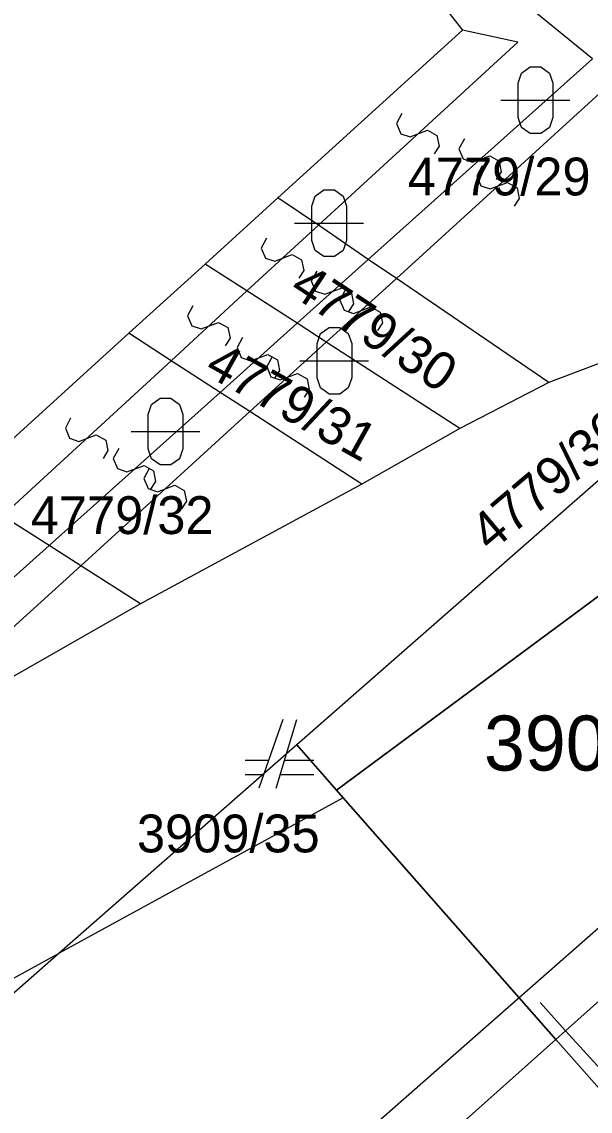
# Model space of a CAD drawing. Extents: x -266179 to -264727, y -1243225 to -1241702.
# Drawn here: x -265077.82 to -265061.28, y -1242723.44 to -1242691.75 of the extents above; entities that cross this region are included whole.
import ezdxf

# ---------------------------------------------------------------- set-up
doc = ezdxf.new("R2010")
doc.units = 0
doc.layers.add('Vrstva 1', color=7, linetype='Continuous')
doc.layers.add('Vrstva 2', color=7, linetype='Continuous')

msp = doc.modelspace()

# ---------------------------------------------------------------- linework, layer by layer
at = {"layer": 'Vrstva 1'}
for p, q in [((-265061.22, -1242692.83), (-265067.36, -1242687.8)), ((-265067.83, -1242688.37), (-265065, -1242691.99)), ((-265065, -1242691.99), (-265070.37, -1242696.87)), ((-265070.37, -1242696.87), (-265072.48, -1242698.8)), ((-265069.19, -1242697.67), (-265070.37, -1242696.87)), ((-265067.74, -1242698.66), (-265069.19, -1242697.67)), ((-265066.92, -1242699.22), (-265067.74, -1242698.66)), ((-265072.48, -1242698.8), (-265074.7, -1242700.81)), ((-265071.27, -1242699.58), (-265072.48, -1242698.8)), ((-265062.49, -1242702.24), (-265066.92, -1242699.22)), ((-265069.81, -1242700.52), (-265071.27, -1242699.58)), ((-265068.96, -1242701.07), (-265069.81, -1242700.52)), ((-265074.7, -1242700.81), (-265079.65, -1242705.31)), ((-265073.47, -1242701.61), (-265074.7, -1242700.81)), ((-265056.26, -1242700.89), (-265069.82, -1242712.78)), ((-265065.08, -1242703.58), (-265068.96, -1242701.07)), ((-265060.13, -1242701.35), (-265062.49, -1242702.24)), ((-265072.05, -1242702.53), (-265073.47, -1242701.61)), ((-265071.18, -1242703.09), (-265072.05, -1242702.53)), ((-265062.49, -1242702.24), (-265065.08, -1242703.58)), ((-265067.93, -1242705.2), (-265071.18, -1242703.09)), ((-265065.08, -1242703.58), (-265067.93, -1242705.2)), ((-265067.93, -1242705.2), (-265074.36, -1242708.68)), ((-265077.02, -1242706.98), (-265078.38, -1242706.12)), ((-265076.1, -1242707.57), (-265077.02, -1242706.98)), ((-265074.36, -1242708.68), (-265076.1, -1242707.57)), ((-265060.96, -1242708.4), (-265068.66, -1242714.1)), ((-265068.66, -1242714.1), (-265060.96, -1242708.4)), ((-265050.06, -1242708.47), (-265063.35, -1242720.14)), ((-265074.36, -1242708.68), (-265082.32, -1242713.22)), ((-265070.22, -1242712.04), (-265070.92, -1242714.04)), ((-265070.42, -1242714.04), (-265069.82, -1242712.04)), ((-265069.82, -1242712.78), (-265076.73, -1242718.84)), ((-265069.82, -1242712.78), (-265068.66, -1242714.1)), ((-265068.66, -1242714.1), (-265069.82, -1242712.78)), ((-265070.64, -1242713.24), (-265071.32, -1242713.24)), ((-265069.32, -1242713.24), (-265070.18, -1242713.24)), ((-265071.32, -1242713.64), (-265070.78, -1242713.64)), ((-265070.3, -1242713.64), (-265069.32, -1242713.64)), ((-265068.66, -1242714.1), (-265068.47, -1242714.32)), ((-265068.47, -1242714.32), (-265068.66, -1242714.1)), ((-265068.47, -1242714.32), (-265076.73, -1242718.84)), ((-265068.47, -1242714.32), (-265063.35, -1242720.14)), ((-265063.35, -1242720.14), (-265068.47, -1242714.32)), ((-265083.25, -1242722.41), (-265076.73, -1242718.84)), ((-265076.73, -1242718.84), (-265081.3, -1242722.85)), ((-265063.35, -1242720.14), (-265075.07, -1242730.43)), ((-265062.28, -1242721.35), (-265063.35, -1242720.14)), ((-265063.35, -1242720.14), (-265062.28, -1242721.35)), ((-265059.6, -1242724.4), (-265062.28, -1242721.35)), ((-265062.28, -1242721.35), (-265059.6, -1242724.4))]:
    msp.add_line(p, q, dxfattribs=at)
for points in [[(-265063.38, -1242693.53), (-265063.28, -1242693.24), (-265063.03, -1242693.06), (-265062.72, -1242693.06), (-265062.47, -1242693.24), (-265062.37, -1242693.53), (-265062.37, -1242694.53), (-265062.47, -1242694.82), (-265062.72, -1242695), (-265063.03, -1242695), (-265063.28, -1242694.82), (-265063.38, -1242694.53)], [(-265069.38, -1242697.11), (-265069.28, -1242696.82), (-265069.03, -1242696.64), (-265068.72, -1242696.64), (-265068.47, -1242696.82), (-265068.37, -1242697.11), (-265068.37, -1242698.11), (-265068.47, -1242698.4), (-265068.72, -1242698.58), (-265069.03, -1242698.58), (-265069.28, -1242698.4), (-265069.38, -1242698.11)], [(-265069.23, -1242701.11), (-265069.13, -1242700.82), (-265068.88, -1242700.64), (-265068.57, -1242700.64), (-265068.32, -1242700.82), (-265068.22, -1242701.11), (-265068.22, -1242702.11), (-265068.32, -1242702.4), (-265068.57, -1242702.58), (-265068.88, -1242702.58), (-265069.13, -1242702.4), (-265069.23, -1242702.11)], [(-265074.14, -1242703.17), (-265074.04, -1242702.88), (-265073.79, -1242702.7), (-265073.48, -1242702.7), (-265073.23, -1242702.88), (-265073.13, -1242703.17), (-265073.13, -1242704.17), (-265073.23, -1242704.46), (-265073.48, -1242704.64), (-265073.79, -1242704.64), (-265074.04, -1242704.46), (-265074.14, -1242704.17)]]:
    msp.add_lwpolyline(points, close=True, dxfattribs=at)
for points in [[(-265063.88, -1242694.03), (-265062.61, -1242694.03), (-265061.88, -1242694.03)], [(-265069.88, -1242697.61), (-265068.61, -1242697.61), (-265067.88, -1242697.61)], [(-265069.73, -1242701.61), (-265068.46, -1242701.61), (-265067.73, -1242701.61)], [(-265074.64, -1242703.67), (-265073.37, -1242703.67), (-265072.64, -1242703.67)]]:
    msp.add_lwpolyline(points, dxfattribs=at)
at = {"layer": 'Vrstva 2'}
for p, q in [((-265063.39, -1242692.34), (-265065, -1242691.99)), ((-265069.19, -1242697.67), (-265063.39, -1242692.34)), ((-265067.74, -1242698.66), (-265061.22, -1242692.83)), ((-265066.92, -1242699.22), (-265061, -1242693.83)), ((-265071.27, -1242699.58), (-265069.19, -1242697.67)), ((-265069.81, -1242700.52), (-265067.74, -1242698.66)), ((-265068.96, -1242701.07), (-265066.92, -1242699.22)), ((-265073.47, -1242701.61), (-265071.27, -1242699.58)), ((-265072.05, -1242702.53), (-265069.81, -1242700.52)), ((-265071.18, -1242703.09), (-265068.96, -1242701.07)), ((-265078.38, -1242706.12), (-265073.47, -1242701.61)), ((-265077.02, -1242706.98), (-265072.05, -1242702.53)), ((-265076.1, -1242707.57), (-265071.18, -1242703.09)), ((-265084.23, -1242713.44), (-265077.02, -1242706.98)), ((-265082.32, -1242713.22), (-265076.1, -1242707.57)), ((-265062, -1242721.1), (-265047.05, -1242707.66)), ((-265062.74, -1242720.28), (-265062, -1242721.1)), ((-265062.28, -1242721.35), (-265062, -1242721.1)), ((-265062, -1242721.1), (-265059.27, -1242724.11)), ((-265062.28, -1242721.35), (-265077.07, -1242734.53))]:
    msp.add_line(p, q, dxfattribs=at)
for points in [[(-265066.761, -1242694.419), (-265066.914, -1242694.71), (-265066.792, -1242695.005), (-265066.52, -1242695.094), (-265066.017, -1242694.903), (-265065.74, -1242695.057), (-265065.675, -1242695.364), (-265065.819, -1242695.591)], [(-265064.943, -1242695.153), (-265065.101, -1242695.441), (-265064.982, -1242695.738), (-265064.711, -1242695.831), (-265064.205, -1242695.647), (-265063.931, -1242695.804), (-265063.87, -1242696.112), (-265064.017, -1242696.337)], [(-265064.428, -1242695.937), (-265064.583, -1242696.227), (-265064.462, -1242696.523), (-265064.191, -1242696.613), (-265063.686, -1242696.424), (-265063.41, -1242696.579), (-265063.347, -1242696.886), (-265063.492, -1242697.113)], [(-265070.701, -1242698.039), (-265070.854, -1242698.33), (-265070.732, -1242698.625), (-265070.46, -1242698.714), (-265069.957, -1242698.523), (-265069.68, -1242698.677), (-265069.615, -1242698.984), (-265069.759, -1242699.211)], [(-265069.239, -1242698.999), (-265069.396, -1242699.288), (-265069.277, -1242699.584), (-265069.006, -1242699.677), (-265068.501, -1242699.491), (-265068.226, -1242699.648), (-265068.164, -1242699.955), (-265068.311, -1242700.181)], [(-265068.407, -1242699.556), (-265068.563, -1242699.846), (-265068.442, -1242700.142), (-265068.171, -1242700.233), (-265067.666, -1242700.045), (-265067.39, -1242700.2), (-265067.327, -1242700.507), (-265067.473, -1242700.734)], [(-265072.842, -1242700.01), (-265072.995, -1242700.301), (-265072.872, -1242700.596), (-265072.6, -1242700.685), (-265072.097, -1242700.493), (-265071.82, -1242700.646), (-265071.755, -1242700.952), (-265071.898, -1242701.18)], [(-265071.393, -1242700.933), (-265071.551, -1242701.222), (-265071.432, -1242701.519), (-265071.161, -1242701.612), (-265070.656, -1242701.427), (-265070.381, -1242701.583), (-265070.32, -1242701.891), (-265070.467, -1242702.117)], [(-265070.538, -1242701.491), (-265070.693, -1242701.781), (-265070.572, -1242702.077), (-265070.301, -1242702.168), (-265069.796, -1242701.98), (-265069.52, -1242702.134), (-265069.457, -1242702.442), (-265069.602, -1242702.669)], [(-265076.396, -1242703.279), (-265076.549, -1242703.57), (-265076.427, -1242703.865), (-265076.155, -1242703.954), (-265075.652, -1242703.763), (-265075.375, -1242703.917), (-265075.31, -1242704.224), (-265075.454, -1242704.451)], [(-265074.998, -1242704.163), (-265075.156, -1242704.451), (-265075.037, -1242704.748), (-265074.766, -1242704.841), (-265074.26, -1242704.657), (-265073.986, -1242704.814), (-265073.925, -1242705.122), (-265074.072, -1242705.347)], [(-265074.108, -1242704.742), (-265074.263, -1242705.032), (-265074.142, -1242705.328), (-265073.871, -1242705.418), (-265073.366, -1242705.229), (-265073.09, -1242705.384), (-265073.027, -1242705.691), (-265073.172, -1242705.918)]]:
    msp.add_lwpolyline(points, dxfattribs=at)

# ---------------------------------------------------------------- texts
at = {"layer": 'Vrstva 1'}
for s, height, p in [('4779/29', 1.1, (-265066.59, -1242696.8)), ('4779/32', 1.1, (-265077.556, -1242706.65)), ('3909/81', 1.6, (-265064.374, -1242713.53)), ('3909/35', 1.1, (-265074.468, -1242715.91))]:
    msp.add_text(s, height=height, dxfattribs=at).set_placement(p)
for s, rotation, p in [('4779/30', 326.5859, (-265070.082, -1242699.641)), ('4779/31', 330.8258, (-265072.547, -1242701.983)), ('4779/36', 40.1643, (-265064.175, -1242707.205))]:
    msp.add_text(s, height=1.1, rotation=rotation, dxfattribs=at).set_placement(p)

doc.saveas('drawing.dxf')
